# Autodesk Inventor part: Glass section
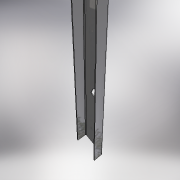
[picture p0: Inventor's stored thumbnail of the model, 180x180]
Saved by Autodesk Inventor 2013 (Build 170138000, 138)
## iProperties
Shininess: 64.0
Length Units: 11269
Angle Units: 11279
Time Units: 11290
Mass Units: 11283
Length Display Precision: 3
Angle Display Precision: 2
Compacted: True
Part Number: Glass section
Document SubType Name: Листовой материал
Created: 2004-12
Material: Stainless Steel, 440C
Designer: =<Author>
Manufacturer: Standard
Standards Organization: Custom
Description: =<Part Number>
Density: 7.75 g/cm^3
Sheet Metal Rule: По умолчанию
Mass: 1662.98 g
Surface Area: 1472.02 cm^2
Volume: 214.578 cm^3
Density: 0.0
Volumn: 0.0
Area: 0.0
PropertySet Name: Model Information
Control State: 0
Master: False
Checked Out: False
Checked Out Date: 2008-10-15
Last Check In Date: 2008-10-15
Толщина: 3.000 mm
Радиус_гибки: 3.000 mm
Ширина_просечки: 3.000 mm
Глубина_просечки: 1.500 mm
Размер_высечки: 12.000 mm
Минимальный_остаток: 6.000 mm
Радиус_перехода: 3.000 mm
JacobiRadiusSize: 3.000 mm
GapSize: 3.000 mm
d0: 40.000 mm
d1: 80.000 mm
d2: 500.000 mm
d3: 3.000 mm
d4: 1.500 mm
d5: 6.000 mm
d6: 3.000 mm
d7: 3.000 mm
d8: 3.000 mm
d9: 25.00 deg
d11: 0.00 deg
d12: 30.000 mm
d13: 25.000 mm
d14: 180.000 mm
d15: 140.000 mm
d16: 3.000 mm
d17: 0.00 deg
d18: 3.000 mm
Author: PVitaliy
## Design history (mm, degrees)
node "ФлнОтгиб1"
feature "Вырез1" dims "d10" = 3 (= Толщина), angle "d11" = 0 deg
feature "Вырез2" dims "d16" = 3 (= Толщина), angle "d17" = 0 deg
feature "УглСкругление1" dims "d18" = 3
body "Solid1"
sketch "Эскиз1"
  geometry: L1 (0, 0)-(0, 40); L2 (0, 40)-(80, 40); L3 (80, 40)-(80, 0)
  constraints: 6 end point, 2 parallel, 1 perpendicular, 1 vertical, 1 other
  dimensions: "d0" = 40 distance of L1.start L1.end; "d1" = 80 distance of L1.end L2.end
feature "Пластина1" dims "d2" = 500, "d3" = 3 (= Ширина_просечки), "d5" = 6 (= Минимальный_остаток), "d7" = 3 (= Радиус_гибки), "d8" = 3, "Толщина" = 3
feature "Изгиб1" dims "d3" = 3 (= Ширина_просечки), "d4" = 1.5 (= Глубина_просечки), "d5" = 6 (= Минимальный_остаток), "d6" = 3 (= Радиус_гибки), "d7" = 3 (= Радиус_гибки), "d8" = 3, "Толщина" = 3, "Зазор_стыка" = 0.01
sketch "Эскиз2"
  geometry: L1 (0, 0)-(68, 0) reference; L2 (74, 0)-(74, -500) reference; L3 (-6, -500)-(-6, 0) reference; L4 (68, 0)-(74, 0) reference; L5 (-6, 0)-(0, 0) reference; L6 (74, 0)-(-6, -37.305)
  constraints: 2 end point, 1 point on line
  dimensions: "d9" = 25 deg angle of L1 L6
sketch "Эскиз3"
  geometry: L1 (68, 497.202)-(0, 465.493) reference; L2 (57.486, 266.107)-(30.297, 253.429); L3 (30.297, 253.429)-(19.732, 276.086); L4 (19.732, 276.086)-(46.921, 288.765); L5 (46.921, 288.765)-(57.486, 266.107); 1 further point
  constraints: 8 end point, 3 parallel, 1 perpendicular
  dimensions: "d12" = 30 distance of L2.start L2.end; "d13" = 25 distance of L2.end L3.end; "d14" = 180 distance between parallel lines of L4 L1; "d15" = 140 distance from line of point (-6, 0) L3
other parameters: "Радиус_гибки" = 3 (= Толщина), "Ширина_просечки" = 3 (= Толщина), "Глубина_просечки" = 1.5 (= 0.5 x Толщина), "Размер_высечки" = 12 (= 4 x Толщина), "Минимальный_остаток" = 6 (= 2 x Толщина), "Радиус_перехода" = 3 (= Радиус_гибки), "JacobiRadiusSize" = 3 (= Толщина), "GapSize" = 3 (= Толщина)
